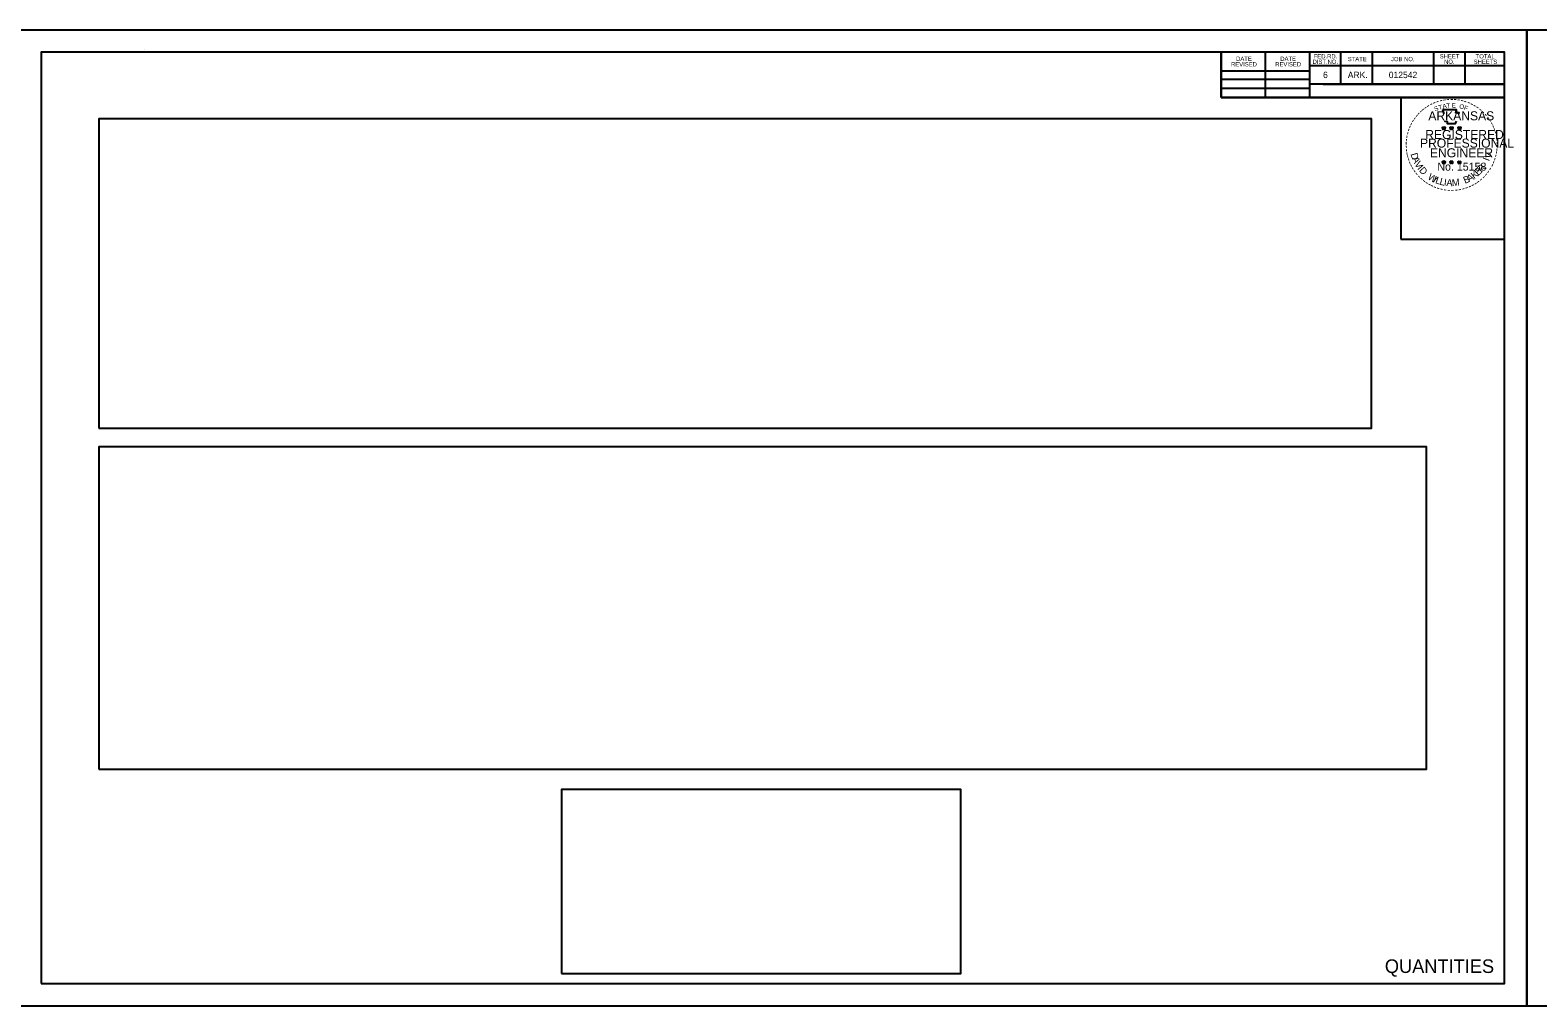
# Model space of a CAD drawing. Extents: x 2260866 to 2265966, y -3124874 to -3123774.
# Drawn here: x 2262578 to 2264278, y -3124874 to -3123774 of the extents above; entities that cross this region are included whole.
import ezdxf

# ---------------------------------------------------------------- set-up
doc = ezdxf.new("R2010")
doc.units = 0
for name, color, linetype in [('Default', 7, 'Continuous'), ('R_Border PE', 7, 'Continuous'), ('SHET_Annotations', 7, 'Continuous'), ('SHET_Border-Lines', 7, 'Continuous'), ('SHET_Border-Text', 7, 'Continuous'), ('SHET_Stamp-PE-Chief-Eng', 7, 'Continuous'), ('SHET_Stamp-Prelim', 7, 'Continuous'), ('SHET_Stamp-Seal', 7, 'Continuous')]:
    doc.layers.add(name, color=color, linetype=linetype)

msp = doc.modelspace()

# ---------------------------------------------------------------- linework, layer by layer
at = {"layer": 'Default'}
for points in [[(2262565.7, -3123773.5), (2262565.7, -3124873.5), (2264265.7, -3124873.5), (2264265.7, -3123773.5)], [(2264265.7, -3123773.5), (2264265.7, -3124873.5), (2265965.7, -3124873.5), (2265965.7, -3123773.5)], [(2262655.6, -3124222.2), (2264090.8, -3124222.2), (2264090.8, -3123873.4), (2262655.6, -3123873.4)], [(2262655.6, -3124606.7), (2264152.8, -3124606.7), (2264152.8, -3124243.4), (2262655.6, -3124243.4)], [(2263177.3, -3124837), (2263627.6, -3124837), (2263627.6, -3124629.8), (2263177.3, -3124629.8)]]:
    msp.add_lwpolyline(points, close=True, dxfattribs=at)
at = {"layer": 'R_Border PE'}
for p, q in [((2264170.5, -3123883.3), (2264172.3, -3123883.8)), ((2264170.5, -3123883.3), (2264171.8, -3123883.5)), ((2264170.5, -3123883.3), (2264171.7, -3123883.9)), ((2264171.2, -3123885.4), (2264172.3, -3123883.8)), ((2264171.2, -3123885.4), (2264171.8, -3123884.1)), ((2264171.2, -3123885.4), (2264172.3, -3123884.3)), ((2264172.3, -3123882), (2264172.1, -3123883.3)), ((2264172.3, -3123883.8), (2264172.3, -3123882)), ((2264172.3, -3123882), (2264172.5, -3123883.3)), ((2264174, -3123883.3), (2264172.3, -3123883.8)), ((2264173.4, -3123885.4), (2264172.3, -3123883.8)), ((2264173.4, -3123885.4), (2264172.3, -3123884.3)), ((2264174, -3123883.3), (2264172.6, -3123883.5)), ((2264173.4, -3123885.4), (2264172.7, -3123883.9)), ((2264174, -3123883.3), (2264173, -3123883.8)), ((2264179, -3123883.3), (2264180.8, -3123883.8)), ((2264179, -3123883.3), (2264180.3, -3123883.5)), ((2264179, -3123883.3), (2264180.2, -3123883.9)), ((2264179.7, -3123885.4), (2264180.8, -3123883.8)), ((2264179.7, -3123885.4), (2264180.3, -3123884.1)), ((2264179.7, -3123885.4), (2264180.8, -3123884.3)), ((2264180.8, -3123882), (2264180.6, -3123883.3)), ((2264180.8, -3123883.8), (2264180.8, -3123882)), ((2264180.8, -3123882), (2264181, -3123883.3)), ((2264182.6, -3123883.3), (2264180.8, -3123883.8)), ((2264181.9, -3123885.4), (2264180.8, -3123883.8)), ((2264181.9, -3123885.4), (2264180.8, -3123884.3)), ((2264182.6, -3123883.3), (2264181.1, -3123883.5)), ((2264181.9, -3123885.4), (2264181.2, -3123883.9)), ((2264182.6, -3123883.3), (2264181.5, -3123883.8)), ((2264188, -3123883.3), (2264189.8, -3123883.9)), ((2264188, -3123883.3), (2264189.3, -3123883.6)), ((2264188, -3123883.3), (2264189.2, -3123884)), ((2264188.7, -3123885.4), (2264189.8, -3123883.9)), ((2264188.7, -3123885.4), (2264189.3, -3123884.2)), ((2264188.7, -3123885.4), (2264189.8, -3123884.3)), ((2264189.8, -3123882), (2264189.6, -3123883.3)), ((2264189.8, -3123883.9), (2264189.8, -3123882)), ((2264189.8, -3123882), (2264190, -3123883.3)), ((2264191.6, -3123883.3), (2264189.8, -3123883.9)), ((2264190.9, -3123885.4), (2264189.8, -3123883.9)), ((2264190.9, -3123885.4), (2264189.8, -3123884.3)), ((2264191.6, -3123883.3), (2264190.1, -3123883.6)), ((2264190.9, -3123885.4), (2264190.2, -3123883.9)), ((2264191.6, -3123883.3), (2264190.5, -3123883.9)), ((2264170.5, -3123921.9), (2264172.3, -3123922.5)), ((2264170.5, -3123921.9), (2264171.8, -3123922.1)), ((2264170.5, -3123921.9), (2264171.7, -3123922.5)), ((2264171.2, -3123924), (2264172.3, -3123922.5)), ((2264171.2, -3123924), (2264171.8, -3123922.7)), ((2264171.2, -3123924), (2264172.2, -3123922.9)), ((2264172.3, -3123920.6), (2264172, -3123921.9)), ((2264173.3, -3123924), (2264172.2, -3123922.9)), ((2264172.3, -3123922.5), (2264172.3, -3123920.6)), ((2264172.3, -3123920.6), (2264172.5, -3123921.9)), ((2264174, -3123921.9), (2264172.3, -3123922.5)), ((2264173.3, -3123924), (2264172.3, -3123922.5)), ((2264174, -3123921.9), (2264172.6, -3123922.2)), ((2264173.3, -3123924), (2264172.6, -3123922.5)), ((2264174, -3123921.9), (2264173, -3123922.4)), ((2264179, -3123921.9), (2264180.8, -3123922.5)), ((2264179, -3123921.9), (2264180.3, -3123922.1)), ((2264179, -3123921.9), (2264180.2, -3123922.5)), ((2264179.7, -3123924), (2264180.8, -3123922.5)), ((2264179.7, -3123924), (2264180.3, -3123922.7)), ((2264179.7, -3123924), (2264180.8, -3123922.9)), ((2264180.8, -3123920.6), (2264180.6, -3123921.9)), ((2264180.8, -3123922.5), (2264180.8, -3123920.6)), ((2264180.8, -3123920.6), (2264181, -3123921.9)), ((2264182.5, -3123921.9), (2264180.8, -3123922.5)), ((2264181.9, -3123924), (2264180.8, -3123922.5)), ((2264181.9, -3123924), (2264180.8, -3123922.9)), ((2264182.5, -3123921.9), (2264181.1, -3123922.2)), ((2264181.9, -3123924), (2264181.2, -3123922.5)), ((2264182.5, -3123921.9), (2264181.5, -3123922.4)), ((2264188, -3123922), (2264189.8, -3123922.5)), ((2264188, -3123922), (2264189.3, -3123922.2)), ((2264188, -3123922), (2264189.2, -3123922.6)), ((2264188.7, -3123924), (2264189.8, -3123922.5)), ((2264188.7, -3123924), (2264189.3, -3123922.8)), ((2264188.7, -3123924), (2264189.8, -3123922.9)), ((2264189.8, -3123920.7), (2264189.6, -3123921.9)), ((2264189.8, -3123922.5), (2264189.8, -3123920.7)), ((2264189.8, -3123920.7), (2264190, -3123921.9)), ((2264191.5, -3123922), (2264189.8, -3123922.5)), ((2264190.9, -3123924), (2264189.8, -3123922.5)), ((2264190.9, -3123924), (2264189.8, -3123922.9)), ((2264191.5, -3123922), (2264190.1, -3123922.2)), ((2264190.9, -3123924), (2264190.2, -3123922.5)), ((2264191.5, -3123922), (2264190.5, -3123922.5))]:
    msp.add_line(p, q, dxfattribs=at)
for points in [[(2264170.7, -3123863.5), (2264172.1, -3123867.7)], [(2264188.6, -3123868.2), (2264189.3, -3123866.8), (2264185.8, -3123866.9), (2264186.6, -3123863.5), (2264170.7, -3123863.5)], [(2264173.2, -3123875.9), (2264173.2, -3123876.3), (2264176.1, -3123876.4), (2264175.8, -3123878.8), (2264185.3, -3123878.8), (2264186.4, -3123876.1)], [(2264180.8, -3123882), (2264181.9, -3123885.4), (2264179, -3123883.3), (2264182.6, -3123883.3), (2264179.7, -3123885.4), (2264180.8, -3123882)], [(2264189.8, -3123882), (2264190.9, -3123885.4), (2264188, -3123883.3), (2264191.6, -3123883.3), (2264188.7, -3123885.4), (2264189.8, -3123882)], [(2264172.3, -3123920.6), (2264173.3, -3123924), (2264170.5, -3123921.9), (2264174, -3123921.9), (2264171.2, -3123924), (2264172.3, -3123920.6)], [(2264180.8, -3123920.6), (2264181.9, -3123924), (2264179, -3123921.9), (2264182.5, -3123921.9), (2264179.7, -3123924), (2264180.8, -3123920.6)], [(2264189.8, -3123920.7), (2264190.9, -3123924), (2264188, -3123922), (2264191.5, -3123922), (2264188.7, -3123924), (2264189.8, -3123920.7)]]:
    msp.add_lwpolyline(points, dxfattribs=at)
for centre, radius in [((2264172.3, -3123883.9), 0.878), ((2264172.3, -3123883.9), 0.737), ((2264172.3, -3123883.9), 0.59), ((2264172.3, -3123883.9), 0.505), ((2264172.3, -3123883.9), 0.381), ((2264172.3, -3123883.9), 0.253), ((2264172.3, -3123883.9), 0.151), ((2264180.8, -3123883.9), 0.878), ((2264180.8, -3123883.9), 0.737), ((2264180.8, -3123883.9), 0.59), ((2264180.8, -3123883.9), 0.505), ((2264180.8, -3123883.9), 0.381), ((2264180.8, -3123883.9), 0.253), ((2264180.8, -3123883.9), 0.151), ((2264189.8, -3123883.9), 0.878), ((2264189.8, -3123883.9), 0.737), ((2264189.8, -3123883.9), 0.59), ((2264189.8, -3123883.9), 0.505), ((2264189.8, -3123883.9), 0.381), ((2264189.8, -3123883.9), 0.253), ((2264189.8, -3123883.9), 0.151), ((2264172.2, -3123922.5), 0.878), ((2264172.2, -3123922.5), 0.737), ((2264172.2, -3123922.5), 0.59), ((2264172.2, -3123922.5), 0.505), ((2264172.2, -3123922.5), 0.381), ((2264172.2, -3123922.5), 0.253), ((2264172.2, -3123922.5), 0.151), ((2264180.8, -3123922.5), 0.878), ((2264180.8, -3123922.5), 0.737), ((2264180.8, -3123922.5), 0.59), ((2264180.8, -3123922.5), 0.505), ((2264180.8, -3123922.5), 0.381), ((2264180.8, -3123922.5), 0.253), ((2264180.8, -3123922.5), 0.151), ((2264189.8, -3123922.5), 0.878), ((2264189.8, -3123922.5), 0.737), ((2264189.8, -3123922.5), 0.59), ((2264189.8, -3123922.5), 0.505), ((2264189.8, -3123922.5), 0.381), ((2264189.8, -3123922.5), 0.253), ((2264189.8, -3123922.5), 0.151)]:
    msp.add_circle(centre, radius, dxfattribs=at)
at = {"layer": 'SHET_Border-Lines'}
for p, q in [((2262706.8, -3123795), (2262706.8, -3123795)), ((2262706.8, -3123795), (2262706.8, -3123795)), ((2263921.2, -3123849.5), (2263921.2, -3123798.5)), ((2263971.1, -3123849.5), (2263971.1, -3123798.5)), ((2264020.9, -3123798.5), (2264020.9, -3123849.5)), ((2264055.8, -3123798.5), (2264055.8, -3123834.3)), ((2264091.2, -3123798.5), (2264091.2, -3123834.3)), ((2264160.4, -3123798.5), (2264160.4, -3123834.3)), ((2264195.8, -3123798.5), (2264195.8, -3123834.3)), ((2264240.7, -3123813.7), (2264020.9, -3123813.7)), ((2264240.7, -3123813.6), (2264240.7, -3123813.6)), ((2263921.2, -3123819.3), (2264020.9, -3123819.3)), ((2263921.2, -3123828.9), (2264020.9, -3123828.9)), ((2264240.7, -3123834.3), (2264020.9, -3123834.3)), ((2264036, -3123834.3), (2264240.7, -3123834.3)), ((2263921.2, -3123838.9), (2264020.9, -3123838.9)), ((2264240.7, -3123849.5), (2263921.2, -3123849.5))]:
    msp.add_line(p, q, dxfattribs=at)
for points in [[(2262565.7, -3124873.5), (2264265.7, -3124873.5), (2264265.7, -3123773.5), (2262565.7, -3123773.5)], [(2264265.7, -3124873.5), (2265965.7, -3124873.5), (2265965.7, -3123773.5), (2264265.7, -3123773.5)], [(2262590.7, -3124848.5), (2264240.7, -3124848.5), (2264240.7, -3123798.5), (2262590.7, -3123798.5)], [(2263921.2, -3123849.5), (2264240.7, -3123849.5), (2264240.7, -3123798.5), (2263921.2, -3123798.5)]]:
    msp.add_lwpolyline(points, close=True, dxfattribs=at)
at = {"layer": 'SHET_Stamp-PE-Chief-Eng'}
msp.add_lwpolyline([(2264172.3, -3123882), (2264173.4, -3123885.4), (2264170.5, -3123883.3), (2264174, -3123883.3), (2264171.2, -3123885.4), (2264172.3, -3123882)], dxfattribs=at)
at = {"layer": 'SHET_Stamp-Prelim'}
msp.add_lwpolyline([(2264130.7, -3123849.5), (2264130.9, -3123849.5), (2264130.9, -3123849.5), (2264130.7, -3123849.5)], close=True, dxfattribs=at)
at = {"layer": 'SHET_Stamp-Seal'}
msp.add_lwpolyline([(2264123.7, -3124009.2), (2264240.7, -3124009.2), (2264240.7, -3123849.5), (2264123.7, -3123849.5)], close=True, dxfattribs=at)

# ---------------------------------------------------------------- texts
at = {"layer": 'Default'}
msp.add_text('QUANTITIES', height=15.35, dxfattribs=at).set_placement((2264105.7, -3124836.5))
at = {"layer": 'R_Border PE'}
for s, height, rotation, p in [('-', 8.16, 10.2193, (2264171.6, -3123855.7)), ('-', 8.16, 5.8968, (2264175.3, -3123855.1)), ('-', 8.16, 0.1862, (2264179.3, -3123854.8)), ('-', 8.16, 357.743, (2264182.9, -3123854.8)), ('-', 8.16, 352.1617, (2264186.7, -3123855.1)), ('-', 8.16, 50.6142, (2264142.9, -3123873.6)), ('-', 8.16, 48.4231, (2264144.9, -3123871.1)), ('-', 8.16, 42.9622, (2264147.2, -3123868.7)), ('-', 8.16, 38.9507, (2264149.4, -3123866.6)), ('-', 8.16, 36.2317, (2264151.9, -3123864.6)), ('-', 8.16, 34.0636, (2264154.8, -3123862.6)), ('-', 8.16, 28.7918, (2264157.9, -3123860.7)), ('-', 8.16, 24.3072, (2264161.1, -3123859.1)), ('S', 5.1, 21.594, (2264162.3, -3123865.1)), ('-', 8.16, 19.1761, (2264164.3, -3123857.8)), ('T', 5.1, 16.4036, (2264167, -3123863.5)), ('-', 8.16, 13.6302, (2264168.1, -3123856.5)), ('A', 5.1, 11.2132, (2264171.2, -3123862.2)), ('T', 5.1, 6.0228, (2264175.5, -3123861.3)), ('E', 5.1, 0.8323, (2264181.2, -3123860.8)), ('O', 5.1, 350.4515, (2264189.3, -3123861.8)), ('-', 8.16, 347.2049, (2264190.4, -3123855.7)), ('F', 5.1, 340.0707, (2264194.2, -3123863)), ('-', 8.16, 342.3362, (2264193.6, -3123856.5)), ('-', 8.16, 337.8551, (2264197.4, -3123857.6)), ('-', 8.16, 334.1211, (2264200.6, -3123859)), ('-', 8.16, 329.6409, (2264203.6, -3123860.5)), ('-', 8.16, 325.8627, (2264206.8, -3123862.3)), ('-', 8.16, 320.5297, (2264210, -3123864.5)), ('-', 8.16, 315.5786, (2264213, -3123867)), ('-', 8.16, 309.8797, (2264215.9, -3123869.8)), ('-', 8.16, 72.3945, (2264135.1, -3123888.7)), ('-', 8.16, 67.7743, (2264136.2, -3123885.4)), ('-', 8.16, 62.8713, (2264137.5, -3123882.3)), ('-', 8.16, 58.0706, (2264139.1, -3123879.2)), ('-', 8.16, 54.2325, (2264140.8, -3123876.5)), ('-', 8.16, 306.6522, (2264218.6, -3123872.8)), ('-', 7.14, 303.6753, (2264221.1, -3123875.7)), ('-', 8.16, 299.6684, (2264222.7, -3123878.8)), ('-', 8.16, 294.6628, (2264224.3, -3123881.9)), ('-', 8.16, 290.5728, (2264225.7, -3123884.9)), ('-', 8.16, 89.0622, (2264132.9, -3123903)), ('-', 8.16, 85.1863, (2264133, -3123899.5)), ('-', 8.16, 81.2013, (2264133.4, -3123895.9)), ('-', 8.16, 75.461, (2264134.1, -3123892.3)), ('-', 8.16, 285.1233, (2264226.8, -3123887.8)), ('-', 8.16, 280.5493, (2264227.9, -3123891.6)), ('-', 8.16, 276.5962, (2264228.7, -3123895.6)), ('-', 8.16, 274.3301, (2264229, -3123899.2)), ('-', 8.16, 269.9407, (2264229.2, -3123902.5)), ('-', 8.16, 94.1959, (2264133.1, -3123906.7)), ('-', 8.16, 98.9479, (2264133.4, -3123910.1)), ('-', 8.16, 101.7149, (2264134.1, -3123913.9)), ('-', 8.16, 105.4578, (2264135, -3123916.9)), ('-', 8.16, 109.0874, (2264136.1, -3123920.1)), ('D', 7.85, 286.2848, (2264134.6, -3123913.2)), ('A', 7.85, 292.7835, (2264136.1, -3123918.3)), ('I', 7.85, 69.0301, (2264223.2, -3123921.8)), ('V', 7.85, 72.6573, (2264224.3, -3123919.1)), ('-', 8.16, 252.8681, (2264227.2, -3123916.3)), ('-', 8.16, 255.7626, (2264228.2, -3123912.6)), ('-', 8.16, 260.9953, (2264228.7, -3123909.2)), ('-', 8.16, 263.5172, (2264229.1, -3123905.9)), ('-', 8.16, 114.0643, (2264137.3, -3123923.2)), ('-', 8.16, 115.7289, (2264138.9, -3123926.3)), ('-', 8.16, 120.4471, (2264140.7, -3123929.3)), ('-', 8.16, 125.8934, (2264142.8, -3123932.2)), ('V', 7.85, 300.7936, (2264138.7, -3123924.3)), ('-', 8.16, 130.7181, (2264145.1, -3123935)), ('I', 7.85, 308.3502, (2264141.9, -3123929.6)), ('D', 7.85, 311.9774, (2264143.7, -3123932)), ('W', 7.85, 328.0731, (2264153.3, -3123941)), ('A', 7.85, 28.9042, (2264200.7, -3123944.9)), ('K', 7.85, 36.9143, (2264206.4, -3123941.7)), ('E', 7.85, 44.0175, (2264211, -3123938.1)), ('R', 7.85, 50.3651, (2264214.8, -3123934.5)), (',', 7.85, 57.4684, (2264218.4, -3123930)), ('-', 8.16, 231.2538, (2264218.5, -3123933)), ('-', 8.16, 233.8452, (2264220.7, -3123930.1)), ('-', 8.16, 239.0712, (2264222.7, -3123926.8)), ('-', 8.16, 244.6197, (2264224.8, -3123923)), ('-', 8.16, 247.8887, (2264226.1, -3123919.7)), ('-', 8.16, 134.2238, (2264147.8, -3123937.8)), ('-', 8.16, 138.9338, (2264150.5, -3123940.1)), ('-', 8.16, 144.6463, (2264153.3, -3123942.2)), ('-', 8.16, 148.0898, (2264156.1, -3123944.1)), ('-', 8.16, 151.5704, (2264159.1, -3123945.7)), ('-', 8.16, 154.6002, (2264161.8, -3123947)), ('I', 7.85, 336.6877, (2264159.3, -3123944.6)), ('-', 8.16, 158.5612, (2264164.9, -3123948.3)), ('L', 7.85, 340.3149, (2264162, -3123945.8)), ('-', 8.16, 162.7983, (2264168.4, -3123949.4)), ('L', 7.85, 346.6625, (2264166.9, -3123947.6)), ('-', 8.16, 167.5555, (2264172.1, -3123950.2)), ('-', 8.16, 173.1155, (2264176, -3123950.8)), ('I', 7.85, 353.0101, (2264172, -3123948.8)), ('A', 7.85, 356.6373, (2264174.9, -3123949.2)), ('-', 8.16, 176.5183, (2264179.8, -3123951.1)), ('-', 8.16, 181.5918, (2264183.6, -3123951)), ('M', 7.85, 4.6473, (2264181.5, -3123949.5)), ('-', 8.16, 185.8167, (2264187.8, -3123950.6)), ('-', 8.16, 191.2858, (2264191.5, -3123949.9)), ('-', 8.16, 195.4743, (2264195.2, -3123948.9)), ('B', 7.85, 22.8589, (2264196.1, -3123946.8)), ('-', 8.16, 199.4643, (2264198.6, -3123947.7)), ('-', 8.16, 204.2516, (2264201.8, -3123946.3)), ('-', 8.16, 207.3568, (2264205, -3123944.6)), ('-', 8.16, 212.2491, (2264207.9, -3123942.9)), ('-', 8.16, 215.7363, (2264210.6, -3123940.9)), ('-', 8.16, 221.0851, (2264213.4, -3123938.5)), ('-', 8.16, 225.7653, (2264216.1, -3123935.9))]:
    msp.add_text(s, height=height, rotation=rotation, dxfattribs=at).set_placement(p)
for s, height, p in [('ARKANSAS', 10.2, (2264154.7, -3123875.2)), ('REGISTERED', 10.2, (2264151.2, -3123896.3)), ('PROFESSIONAL', 10.2, (2264145.3, -3123906)), ('ENGINEER', 10.2, (2264156.5, -3123916.9)), ('No. 15158', 8.96, (2264164.9, -3123931.9)), ('AAMU', 0.000102, (2264180.4, -3123949.5))]:
    msp.add_text(s, height=height, dxfattribs=at).set_placement(p)
at = {"layer": 'SHET_Annotations'}
for s, p in [('6', (2264036, -3123827.6)), ('ARK.', (2264063.9, -3123827.6)), ('012542', (2264110.1, -3123827.6))]:
    msp.add_text(s, height=7.2, dxfattribs=at).set_placement(p)
at = {"layer": 'SHET_Border-Text'}
for s, p in [('FED.RD.', (2264025.5, -3123805.4)), ('SHEET', (2264167.6, -3123805.4)), ('TOTAL', (2264208.1, -3123805.4)), ('REVISED', (2263932.3, -3123814.4)), ('DATE', (2263938, -3123808.2)), ('REVISED', (2263982.1, -3123814.4)), ('DATE', (2263987.8, -3123808.2)), ('DIST.NO.', (2264024.2, -3123811.6)), ('STATE', (2264063.9, -3123808.5)), ('JOB NO.', (2264112.6, -3123808.5)), ('NO.', (2264172.5, -3123811.6)), ('SHEETS', (2264205.9, -3123811.6))]:
    msp.add_text(s, height=4.8, dxfattribs=at).set_placement(p)
at = {"layer": 'SHET_Stamp-Prelim'}
for s, height in [('PRELIMINARY', 0.013), ('SUBJECT TO REVISION', 0.009)]:
    msp.add_text(s, height=height, dxfattribs=at).set_placement((2264130.7, -3123849.5))

doc.saveas('drawing.dxf')
